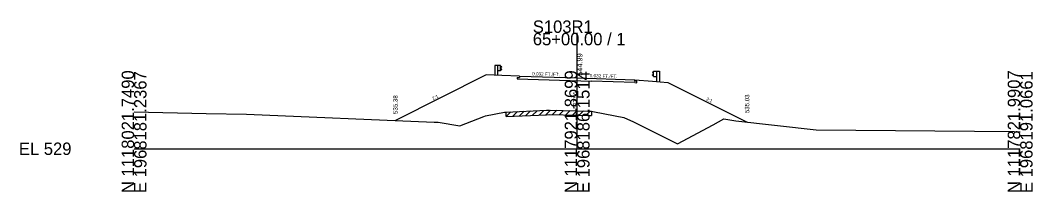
# Model space of a CAD drawing. Extents: x -26 to 203, y -10 to 12018.
# Drawn here: x -25.7 to 202.8, y 5490.3 to 5529 of the extents above; entities that cross this region are included whole.
import ezdxf

# ---------------------------------------------------------------- set-up
doc = ezdxf.new("R2010")
doc.units = 0
for name, color, linetype in [('Level 10', 7, 'Continuous'), ('Level 11', 7, 'Continuous'), ('Level 12', 7, 'Continuous'), ('Level 24', 7, 'Continuous'), ('Level 32', 7, 'Continuous'), ('Level 33', 7, 'Continuous'), ('Level 59', 7, 'Continuous'), ('Level 6', 7, 'Continuous'), ('Level 60', 7, 'Continuous'), ('Level 61', 7, 'Continuous'), ('Level 63', 7, 'Continuous'), ('Level 7', 7, 'Continuous')]:
    doc.layers.add(name, color=color, linetype=linetype)

msp = doc.modelspace()

# ---------------------------------------------------------------- linework, layer by layer
at = {"layer": 'Level 11'}
for p, q in [((113, 5515.27), (113, 5515.58)), ((113.5, 5515.25), (113, 5515.27)), ((113, 5514.91), (113.5, 5514.89)), ((113.5, 5514.89), (113.5, 5515.25))]:
    msp.add_line(p, q, dxfattribs=at)
at = {"layer": 'Level 12'}
for p, q in [((86.5, 5516.11), (87, 5516.09)), ((86.5, 5516.11), (86.5, 5515.75)), ((86.5, 5515.75), (103.21, 5515.22)), ((87, 5516.4), (87, 5516.09)), ((113, 5514.91), (103.21, 5515.22))]:
    msp.add_line(p, q, dxfattribs=at)
at = {"layer": 'Level 24'}
for p, q in [((81.4, 5518.78), (81.4, 5516.58)), ((82.06, 5518.78), (81.4, 5518.78)), ((82.06, 5518.78), (82.06, 5516.56)), ((82.73, 5518.78), (82.06, 5518.78)), ((82.73, 5517.61), (82.06, 5517.61)), ((82.73, 5517.61), (82.73, 5518.78)), ((82.73, 5518.71), (83, 5518.51)), ((83, 5518.46), (82.73, 5518.26)), ((83, 5517.94), (82.73, 5518.14)), ((82.73, 5517.69), (83, 5517.89)), ((83, 5518.51), (83, 5518.46)), ((83, 5517.89), (83, 5517.94)), ((117.27, 5517.43), (117, 5517.23)), ((117, 5517.23), (117, 5517.18)), ((117, 5517.18), (117.27, 5516.98)), ((117, 5516.66), (117.27, 5516.86)), ((117.27, 5516.33), (117.27, 5517.5)), ((117.27, 5517.5), (117.94, 5517.5)), ((117.94, 5517.5), (117.94, 5515.17)), ((117.94, 5517.5), (118.6, 5517.5)), ((118.6, 5517.5), (118.6, 5515.12)), ((117, 5516.61), (117, 5516.66)), ((117.27, 5516.41), (117, 5516.61)), ((117.27, 5516.33), (117.94, 5516.33))]:
    msp.add_line(p, q, dxfattribs=at)
at = {"layer": 'Level 59'}
for p, q in [((87, 5516.4), (100, 5515.99)), ((100, 5515.99), (113, 5515.58))]:
    msp.add_line(p, q, dxfattribs=at)
at = {"layer": 'Level 6'}
for p, q in [((83, 5516.53), (79.5, 5516.64)), ((87, 5516.4), (83, 5516.53)), ((113, 5515.58), (117, 5515.25)), ((117, 5515.25), (120.5, 5514.96))]:
    msp.add_line(p, q, dxfattribs=at)
at = {"layer": 'Level 60'}
for p, q in [((0, 5508.32), (16.28, 5507.97)), ((16.28, 5507.97), (25.36, 5507.77)), ((25.36, 5507.77), (67.73, 5506.02)), ((79.32, 5507.39), (83.64, 5508.23)), ((83.64, 5508.23), (83.96, 5508.28)), ((83.96, 5508.28), (93.06, 5508.68)), ((93.06, 5508.68), (93.75, 5508.71)), ((93.75, 5508.71), (100, 5508.56)), ((100, 5508.56), (102.42, 5508.5)), ((102.42, 5508.5), (103.21, 5508.48)), ((103.21, 5508.48), (103.89, 5508.33)), ((103.89, 5508.33), (110.51, 5507.05)), ((67.73, 5506.02), (68.67, 5505.99)), ((68.67, 5505.99), (73.53, 5505.17)), ((73.53, 5505.17), (78.91, 5507.24)), ((78.91, 5507.24), (79.32, 5507.39)), ((110.51, 5507.05), (112.7, 5506.06)), ((112.7, 5506.06), (122.69, 5501.12)), ((122.69, 5501.12), (130.73, 5505.43)), ((130.73, 5505.43), (133.12, 5506.77)), ((133.12, 5506.77), (135.79, 5506.31)), ((135.79, 5506.31), (153.95, 5504.3)), ((153.95, 5504.3), (198.68, 5503.86)), ((198.68, 5503.86), (200, 5503.83))]:
    msp.add_line(p, q, dxfattribs=at)
at = {"layer": 'Level 61'}
for p, q in [((83.96, 5507.28), (85.01, 5508.33)), ((83.96, 5507.28), (83.96, 5508.28)), ((83.96, 5507.28), (93.06, 5507.68)), ((85.46, 5507.35), (86.51, 5508.4)), ((86.96, 5507.42), (88.01, 5508.46)), ((88.46, 5507.48), (89.51, 5508.53)), ((89.96, 5507.55), (91.01, 5508.59)), ((91.46, 5507.61), (92.51, 5508.66)), ((92.96, 5507.68), (93.99, 5508.71)), ((93.06, 5507.68), (93.75, 5507.71)), ((93.75, 5507.71), (100, 5507.56)), ((94.46, 5507.7), (95.44, 5508.67)), ((95.96, 5507.66), (96.94, 5508.64)), ((97.46, 5507.62), (98.44, 5508.6)), ((98.96, 5507.59), (99.94, 5508.56)), ((100.46, 5507.55), (101.44, 5508.53)), ((101.96, 5507.52), (102.93, 5508.49)), ((103.21, 5508.48), (103.21, 5507.48)), ((100, 5507.56), (102.42, 5507.5)), ((102.42, 5507.5), (103.21, 5507.48))]:
    msp.add_line(p, q, dxfattribs=at)
at = {"layer": 'Level 63'}
for p, q in [((100, 5500), (100, 5526.14)), ((0, 5500), (100, 5500)), ((100, 5500), (200, 5500))]:
    msp.add_line(p, q, dxfattribs=at)
at = {"layer": 'Level 7'}
for p, q in [((79.5, 5516.64), (58.98, 5506.38)), ((120.5, 5514.96), (138.36, 5506.03))]:
    msp.add_line(p, q, dxfattribs=at)

# ---------------------------------------------------------------- texts
at = {"layer": 'Level 10'}
msp.add_text(' 537.56', height=0.9, rotation=90, dxfattribs=at).set_placement((100, 5508.7))
at = {"layer": 'Level 32'}
for s, rotation, p in [('0.032 FT./FT.', 358.1901, (89.84, 5516.56)), ('0.032 FT./FT.', 358.1901, (102.84, 5516.15)), ('2:1', 26.5651, (67.5, 5510.92)), ('2:1', 333.4349, (129.04, 5510.97))]:
    msp.add_text(s, height=0.75, rotation=rotation, dxfattribs=at).set_placement(p)
at = {"layer": 'Level 33'}
for s, p in [('535.38', (59.48, 5507.84)), ('535.03', (138.86, 5508.03))]:
    msp.add_text(s, height=1, rotation=90, dxfattribs=at).set_placement(p)
at = {"layer": 'Level 59'}
msp.add_text(' 544.99', height=1.2, rotation=90, dxfattribs=at).set_placement((101.2, 5515.99))
at = {"layer": 'Level 63'}
for s, p in [('S103R1', (90, 5526.14)), ('65+00.00 / 1', (90, 5523.34)), ('EL 529', (-26, 5498.6))]:
    msp.add_text(s, height=2.8, dxfattribs=at).set_placement(p)
for s, p in [('N 1118021.7490', (0, 5490)), ('E 1968181.2367', (2.8, 5490)), ('N 1117921.8699', (100, 5490)), ('E 1968186.1514', (102.8, 5490)), ('N 1117821.9907', (200, 5490)), ('E 1968191.0661', (202.8, 5490))]:
    msp.add_text(s, height=2.8, rotation=90, dxfattribs=at).set_placement(p)

doc.saveas('drawing.dxf')
